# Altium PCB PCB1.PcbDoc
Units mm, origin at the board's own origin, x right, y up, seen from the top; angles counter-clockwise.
Board outline 67 x 39 mm, 2 copper layers (Top Layer, Bottom Layer); 18 components, 9 nets, 46 pads, 0 vias.
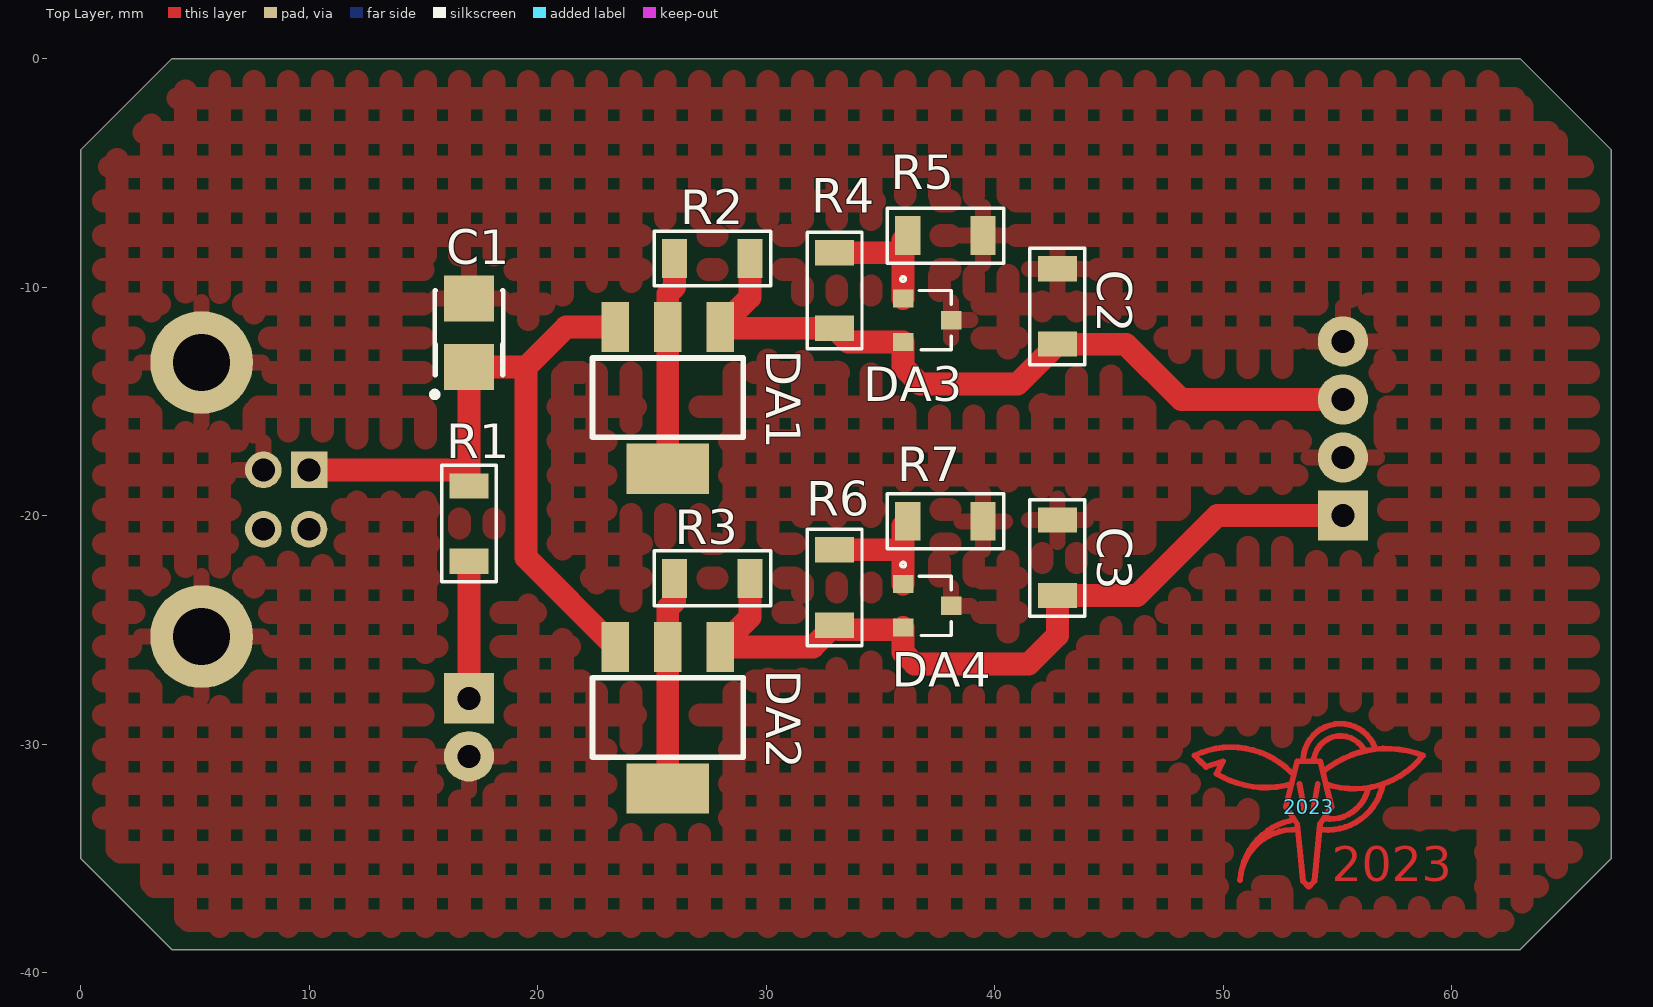
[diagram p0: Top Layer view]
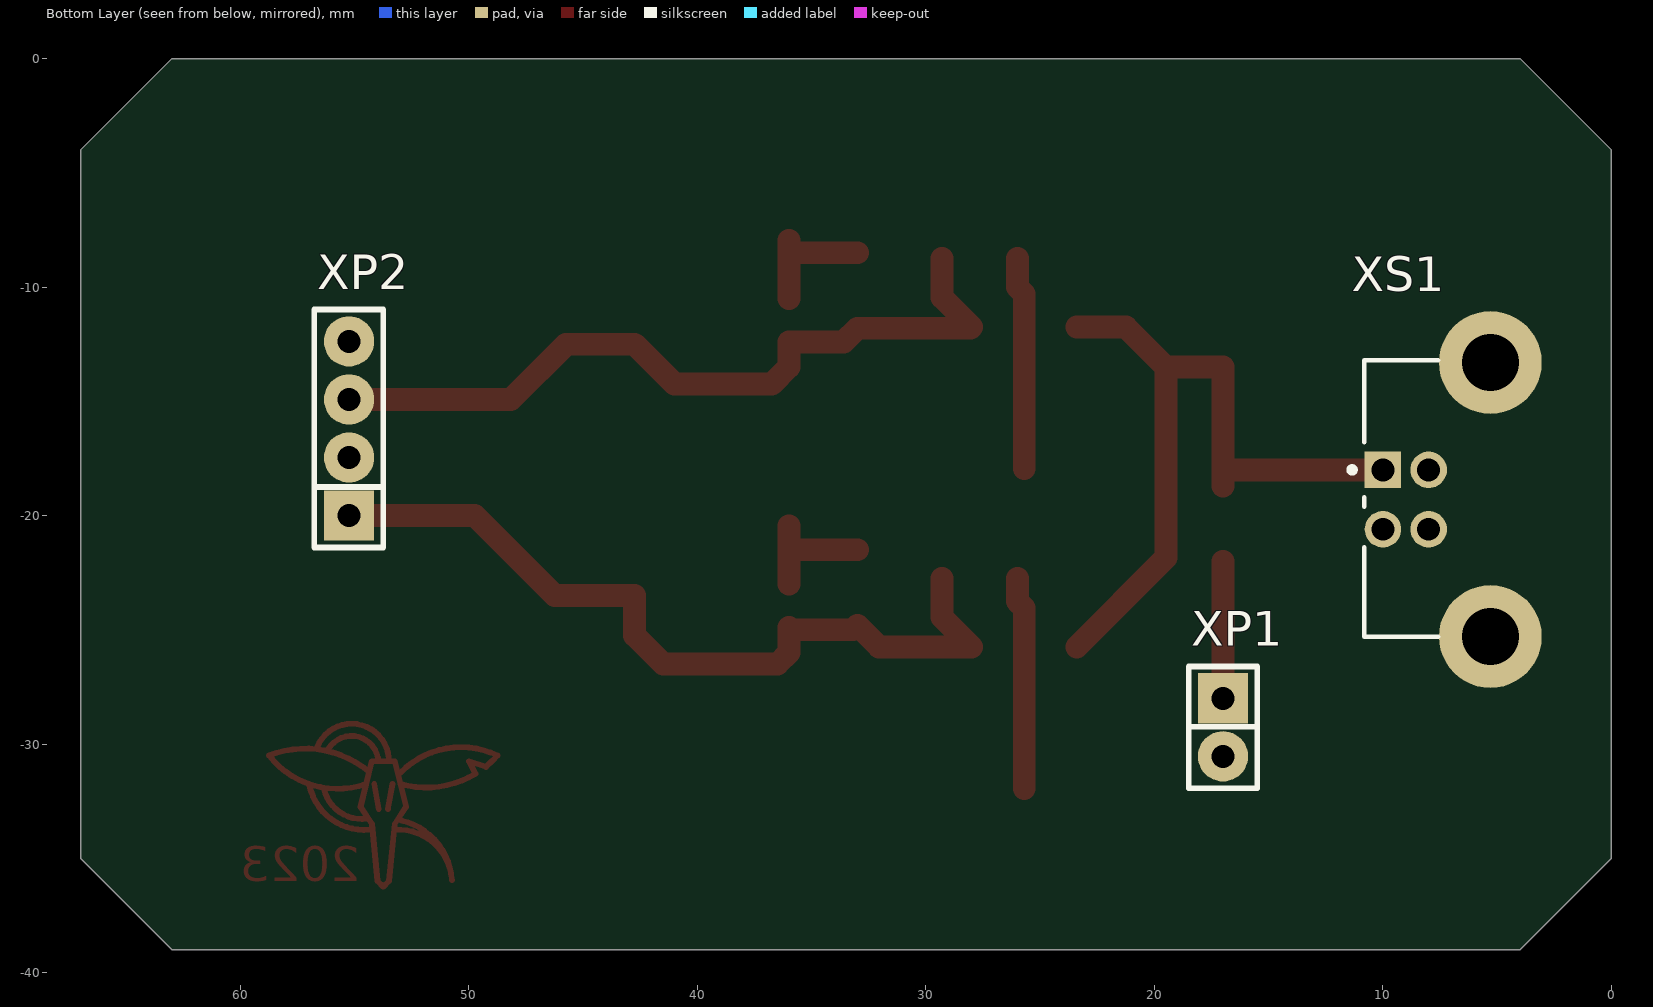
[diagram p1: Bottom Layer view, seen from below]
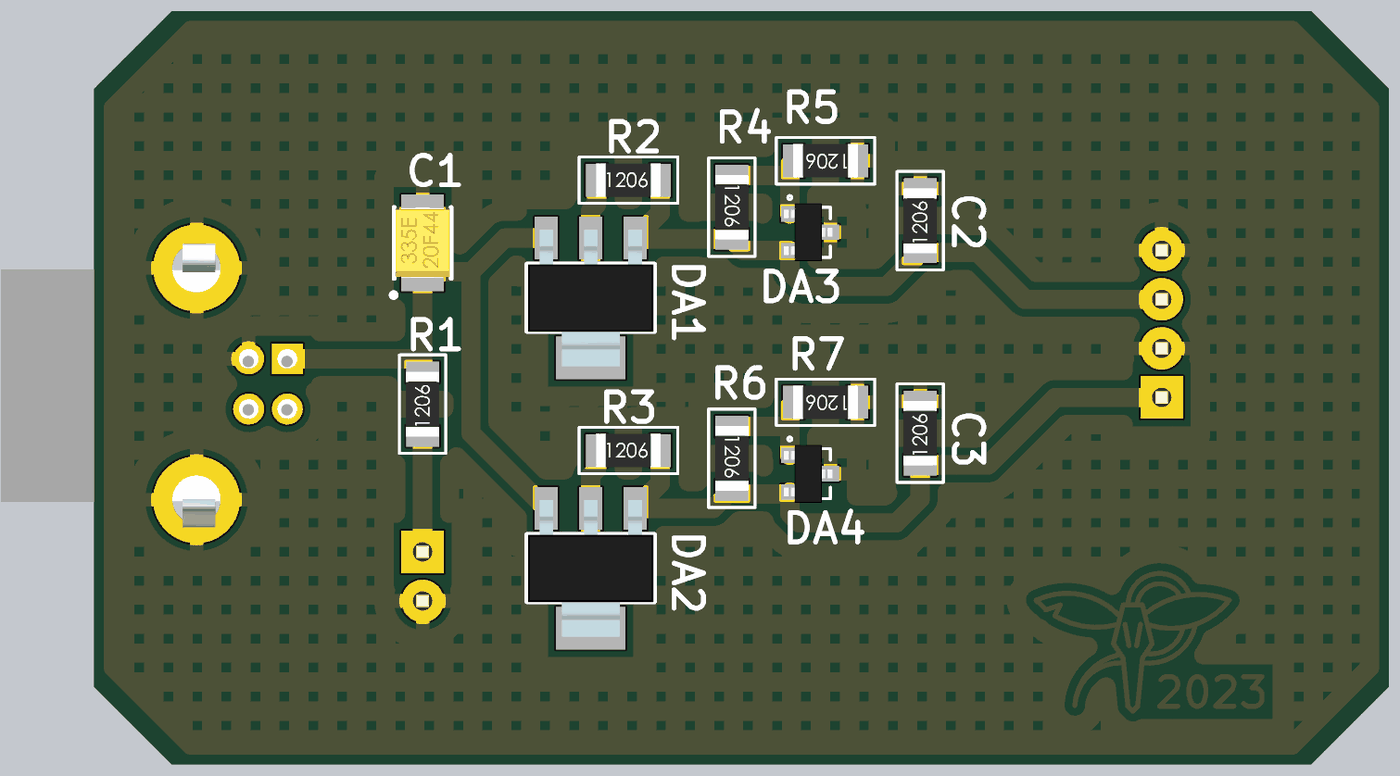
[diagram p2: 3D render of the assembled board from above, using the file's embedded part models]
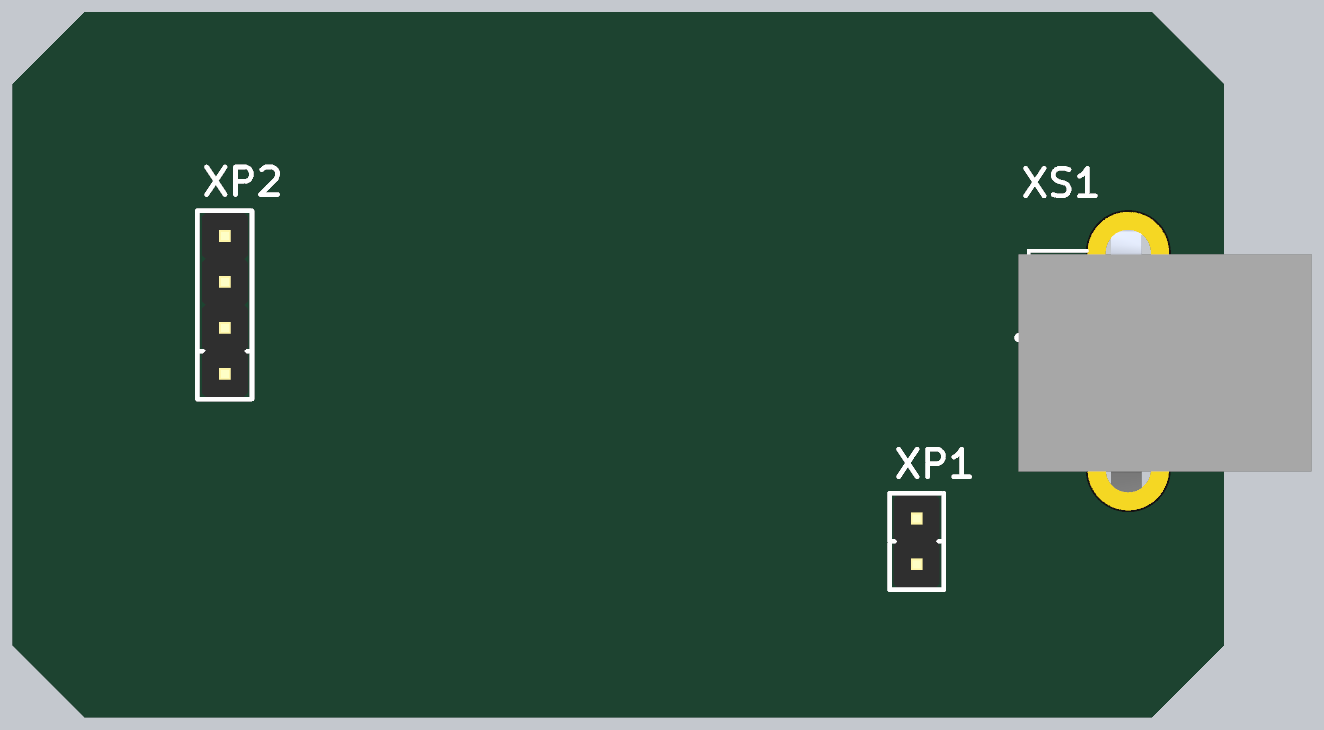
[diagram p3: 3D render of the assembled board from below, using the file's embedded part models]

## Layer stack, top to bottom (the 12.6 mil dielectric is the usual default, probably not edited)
Top Layer: signal copper 0.0356
Dielectric: dielectric 0.32, FR-4, Dk 4.8
Bottom Layer: signal copper 0.0356

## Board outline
0,-35 0,-4 4,0 63,0 67,-4 67,-35 63,-39 4,-39

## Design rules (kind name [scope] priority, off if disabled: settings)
Clearance Clearance_poly [InPolygon] p1: gap=0.4
Clearance [All] p2: gap=0.2
ComponentClearance [All] p1: gap=0.25 collisioncheckmode=3 verticalgap=0.25 showdistances=FALSE
Height [All] p1: minheight=0 maxheight=45 prefheight=12.7
PolygonConnect [All] p1: connectstyle=Relief reliefconductorwidth=0.7 reliefentries=4 polygonreliefangle="90 Angle"
RoutingVias [All] p1: holewidth=0.7 width=1.3 viastyle="Through Hole" minholewidth=0.5 minwidth=1 maxholewidth=1 maxwidth=1.5
SilkscreenOverComponentPads [All] p1: minsilkscreentomaskgap=0.254
SolderMaskExpansion [All] p1: expansion=0.102
Width [All] p1: maxlimit=5 minlimit=0.3 preferedwidth=0.7
25 further rules are at their usual default settings.

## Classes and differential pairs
component class Sch1: C1 C2 C3 DA1 DA2 DA3 DA4 R1 R2 R3 R4 R5 R6 R7 XP1 XP2 XS1

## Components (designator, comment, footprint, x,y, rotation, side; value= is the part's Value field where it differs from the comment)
2023 "2023" "Rat's logo" 53.75,-32.75 r0 top
C1 "Type B" "Type B" 17,-12 r90 top
C2 "C_1206" RC_1206 42.75,-12.5 r90 top
C3 "C_1206" RC_1206 42.75,-23.5 r90 top
DA1 "LM317" SOT-223 28,-11.75 r180 top
DA2 "LM317" SOT-223 28,-25.75 r180 top
DA3 "TLVH431" SOT-23 36,-10.5 r270 top
DA4 "TLVH431" SOT-23 36,-23 r270 top
R1 "R_1206" RC_1206 17,-22 r90 top
R2 "R_1206" RC_1206 26,-8.75 r0 top
R3 "R_1206" RC_1206 26,-22.75 r0 top
R4 "R_1206" RC_1206 33,-8.5 r270 top
R5 "R_1206" RC_1206 39.5,-7.75 r180 top
R6 "R_1206" RC_1206 33,-21.5 r270 top
R7 "R_1206" RC_1206 39.5,-20.25 r180 top
XP1 "LED" PLS-2 17,-28 r270 bottom
XP2 "Bat" PLS-4 55.25,-20 r90 bottom
XS1 "USB-B" USB-B 10,-18 r90 bottom

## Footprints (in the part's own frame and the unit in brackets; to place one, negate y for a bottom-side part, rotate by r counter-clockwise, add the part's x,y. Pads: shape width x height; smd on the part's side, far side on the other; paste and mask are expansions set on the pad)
PLS-2 [mm]
  rect 2.2x2.2 hole 1: 1(0,0)
  round 2.2 hole 1: 2(2.54,0)
  silkscreen extent -1.4,-1.5 3.94,1.5, body extent -1.27,-1.27 3.81,1.27, height 8.54
PLS-4 [mm]
  rect 2.2x2.2 hole 1: 1(0,0)
  round 2.2 hole 1: 2(2.54,0) 3(5.08,0) 4(7.62,0)
  silkscreen extent -1.4,-1.5 9.02,1.52, body extent -1.27,-1.27 8.89,1.27, height 8.54
"Rat's logo" [mm]
  Top Layer lines w0.254: -4.516,1.786 cw(c-1.875,5.025) -5,2.25 cw(c-3.402,-1.109) -0.75,1.5 ; -4.5,1.75 -3.75,2 -4,1.5 ; -4.033,1.446 ccw(c-1.875,5.025) -0.75,1 ; -0.8,-0.6 ccw(c-0.153,-3.378) -3,-3.2 cw(c-0.65,-3.35) -0.5,-1 ; -0.4,1 -0.2,-0.1 ; -0.238,2.147 cw(c1.384,2.012) 2.9,2.6 ; 0.2,-0.1 0.4,1 ; 0.239,2.148 cw(c1.394,1.929) 2.395,2.546 ; 0.6,-1 ccw(c0.831,1.445) 3.23,0.923 ; 0.652,1.562 cw(c3.411,-1.797) 5,2.25 cw(c2,4.6) 0.75,1 ; 0.711,-0.52 ccw(c0.937,1.169) 2.6,0.8 ; -1,0 -0.5,2 0.5,2 1,0 0.5,-0.75 0.25,-3.25 0,-3.5 -0.25,-3.25 -0.5,-0.75 -1,0
RC_1206 [mm]
  rect 1.1x1.7 smd: 1(0,0) 2(3.3,0)
  silkscreen extent -0.9,-1.2 4.2,1.2, body extent -0.02,-0.86 3.33,0.87, height 0.85
SOT-23 [mm]
  rect 0.8x0.9 smd: 1(0,0) 2(1.9,0) 3(0.95,2.1)
  silkscreen extent -0.95,-0.1 2.25,2.1, body extent -0.55,-0.3 2.45,2.2, height 1.06
SOT-223 [mm]
  rect 1.2x2.2 smd: 1(0,0) 2(2.3,0) 3(4.6,0)
  rect 3.6x2.2 smd: 2(2.3,6.2)
  silkscreen extent -1,1.35 5.6,4.83, body extent -0.95,-0.44 5.55,6.64, height 1.65
"Type B" [mm]
  rect 2x2.2 smd: 1(-1.5,0) 2(1.5,0)
  silkscreen extent -2.82,-1.5 1.85,1.62, body extent -1.83,-1.4 1.83,1.4, height 1.89
USB-B [mm]
  rect 1.6x1.6 hole 1: 1(0,0)
  round 1.6 hole 1: 2(-2.6,0) 3(-2.6,-2) 4(0,-2)
  round 4.5 hole 2.5: 4(-7.3,-4.7) 4(4.7,-4.7)
  silkscreen extent -7.3,-2.41 4.8,1.47, body extent -8.74,-14.83 5.95,1.37, height 10.7

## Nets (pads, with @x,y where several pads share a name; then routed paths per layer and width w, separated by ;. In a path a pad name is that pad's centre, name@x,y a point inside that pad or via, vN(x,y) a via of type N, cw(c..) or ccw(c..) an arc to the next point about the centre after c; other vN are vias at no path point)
GND: C1.2 C2.2 C3.2 DA3.3 DA4.3 R5.1 R7.1 XP1.2 XP2.2 XP2.4 XS1.4
NetC1_1: C1.1 DA1.3 DA2.3 R1.2 XS1.1 | length 33.2
  Top Layer w1: XS1.1 17,-18 ; R1.2 17,-18 ; DA2.3 19.5,-21.85 19.5,-13.5 ; DA1.3 21.25,-11.75 19.5,-13.5 ; 17,-18 C1.1 19.5,-13.5
NetC2_1: C2.1 DA1.1 DA3.2 R2.2 R4.2 XP2.3 | length 34.1
  Top Layer w1: DA1.1 29.3,-10.45 R2.2 ; DA1.1@28.05,-11.8 R4.2 33.6,-12.4 DA3.2 36,-13.5 36.75,-14.25 41,-14.25 C2.1 45.75,-12.5 48.17,-14.92 XP2.3
NetC3_1: C3.1 DA2.1 DA4.2 R3.2 R6.2 XP2.1 | length 36.3
  Top Layer w1: R3.2 29.3,-24.45 DA2.1 32.05,-25.75 R6.2 33.2,-25 35.9,-25 DA4.2 36,-26 36.5,-26.5 41.5,-26.5 42.75,-25.25 C3.1 46.25,-23.5 49.75,-20 XP2.1
NetDA1_2: DA1.2 R2.1 | length 9.3
  Top Layer w1: DA1.2@25.7,-17.95 25.7,-11.75 25.7,-10.3 26,-10 R2.1
NetDA2_2: DA2.2 R3.1 | length 9.3
  Top Layer w1: DA2.2@25.7,-31.95 25.7,-25.75 25.7,-24.05 26,-23.75 R3.1
NetDA3_1: DA3.1 R4.1 R5.2 | length 5.5
  Top Layer w1: R4.1 R5.2@36,-8.5 ; DA3.1 R5.2@36,-8.5 ; R5.2@36,-7.95 R5.2@36,-8.5
NetDA4_1: DA4.1 R6.1 R7.2 | length 5.6
  Top Layer w1: R6.1 36,-21.5 ; DA4.1 36,-21.5 ; R7.2@36,-20.45 36,-21.5
NetR1_1: R1.1 XP1.1 | length 6
  Top Layer w1: XP1.1 R1.1
pads on no net: XS1.2 XS1.3

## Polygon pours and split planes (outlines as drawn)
GND on Top Layer "Top Layer GND" (hatched 90Degree grid 1.5 track 1, remove dead copper, pour order 4): 1,-5 5,-1 62,-1 66,-5 66,-34 62,-38 5,-38 1,-34

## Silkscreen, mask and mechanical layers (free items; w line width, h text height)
Mechanical 32:
  the board outline again, w0.5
